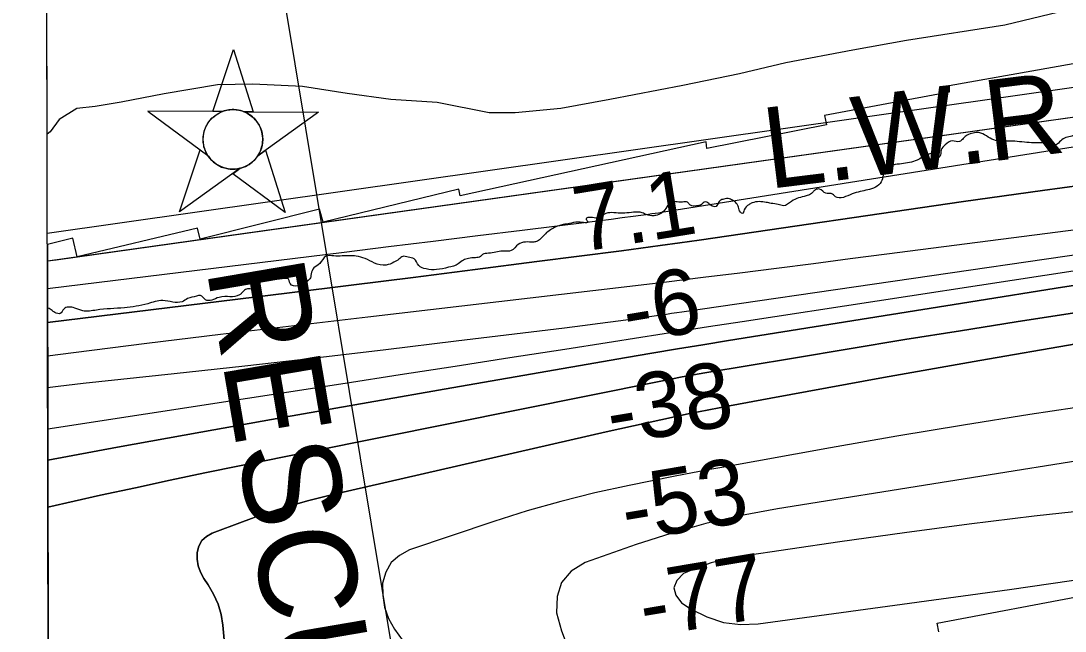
# Model space of a CAD drawing. Extents: x 3355677 to 3393573, y 612928 to 638357.
# Drawn here: x 3359768 to 3360838, y 623686 to 624311 of the extents above; entities that cross this region are included whole.
import ezdxf

# ---------------------------------------------------------------- set-up
doc = ezdxf.new("R2010")
doc.units = 0
for name, color, linetype in [('V-CHAN-NAID', 7, 'Continuous'), ('V-GRID-FRAM', 7, 'Continuous'), ('V-RIVR-EDGE', 7, 'Continuous'), ('V-RIVR-RANG', 7, 'Continuous'), ('V-RRAP-RVMT', 7, 'Continuous'), ('V-SITE-VEGE', 7, 'Continuous'), ('V-TOPO-DPTH', 7, 'Continuous'), ('V-TOPO-MAJR', 7, 'Continuous'), ('V-TOPO-MINR', 7, 'Continuous'), ('V-TOPO-WATR', 7, 'Continuous'), ('V-TOPO-WATR-IDEN', 7, 'Continuous')]:
    doc.layers.add(name, color=color, linetype=linetype)

msp = doc.modelspace()

# ---------------------------------------------------------------- linework, layer by layer
at = {"layer": 'V-CHAN-NAID'}
for points in [[(3359974.3, 624218), (3359964.7, 624218.1), (3359985.8, 624281.6), (3360006, 624217.8), (3359996.5, 624217.8), (3359994.9, 624218.4), (3359992.8, 624219), (3359990.7, 624219.5), (3359988.7, 624219.8), (3359987.5, 624219.9), (3359986, 624220), (3359984.3, 624220), (3359982.9, 624219.9), (3359981, 624219.7), (3359979.6, 624219.5), (3359977.9, 624219.1), (3359976.3, 624218.7), (3359975.3, 624218.4)], [(3359974.3, 624218), (3359897.8, 624218.5), (3359959.4, 624173.1), (3359958.2, 624175.1), (3359957.4, 624176.7), (3359956.6, 624178.6), (3359955.9, 624180.7), (3359955.5, 624182), (3359955.2, 624183.7), (3359954.9, 624185.1), (3359954.7, 624186.7), (3359954.6, 624188.4), (3359954.6, 624190), (3359954.7, 624192.1), (3359954.9, 624193.7), (3359955.3, 624195.9), (3359955.8, 624197.8), (3359956.4, 624199.7), (3359957, 624201.4), (3359957.8, 624203), (3359958.6, 624204.5), (3359959.6, 624206.3), (3359960.7, 624207.7), (3359961.7, 624209), (3359962.7, 624210.1), (3359964, 624211.5), (3359965, 624212.4), (3359966.8, 624213.8), (3359968, 624214.7), (3359969.7, 624215.8), (3359971.4, 624216.7), (3359972.8, 624217.4)], [(3359996.5, 624217.8), (3360072.9, 624217.3), (3360010.7, 624172.8), (3360011.7, 624174.3), (3360012.6, 624176.1), (3360013.3, 624177.7), (3360014.1, 624179.7), (3360014.6, 624181.4), (3360015, 624183.1), (3360015.4, 624185.1), (3360015.6, 624186.7), (3360015.7, 624188.9), (3360015.7, 624190.9), (3360015.5, 624193.2), (3360015.2, 624194.9), (3360014.7, 624197.1), (3360014.1, 624199.3), (3360013.3, 624201.3), (3360012.7, 624202.7), (3360011.7, 624204.6), (3360010.6, 624206.3), (3360009.4, 624208), (3360008.1, 624209.6), (3360006.9, 624211), (3360005.2, 624212.5), (3360003.5, 624213.9), (3360001.8, 624215.1), (3359999.9, 624216.2), (3359998.5, 624217)], [(3359992.7, 624159.9), (3359930.5, 624115.4), (3359951.6, 624178.8), (3359959.4, 624173.1), (3359960, 624172.2), (3359961.4, 624170.3), (3359962.6, 624168.9), (3359964, 624167.4), (3359965.4, 624166.2), (3359966.9, 624165), (3359968.3, 624164), (3359970, 624163), (3359971.7, 624162.1), (3359973.5, 624161.2), (3359974.9, 624160.7), (3359976.6, 624160.2), (3359978.8, 624159.6), (3359980.3, 624159.3), (3359982.3, 624159.1), (3359983.9, 624159), (3359985.7, 624158.9), (3359987.4, 624159), (3359989.1, 624159.2), (3359991, 624159.5)], [(3360010.7, 624172.8), (3360018.5, 624178.4), (3360038.8, 624114.6), (3359984.9, 624154.3), (3359992.7, 624159.9), (3359994.4, 624160.3), (3359996, 624160.9), (3359998.1, 624161.8), (3359999.9, 624162.7), (3360001.7, 624163.8), (3360003.5, 624165), (3360005, 624166.3), (3360006.3, 624167.4), (3360007.7, 624168.9), (3360008.9, 624170.3), (3360010, 624171.7)]]:
    msp.add_lwpolyline(points, close=True, dxfattribs=at)
msp.add_circle((3359985.2, 624189.5), 30.5, dxfattribs=at)
at = {"layer": 'V-GRID-FRAM'}
msp.add_lwpolyline([(3359767.9, 636495.9), (3391341.6, 636578.5), (3391397.2, 618394.8), (3359807.6, 618312.1), (3359767.9, 636495.9)], dxfattribs=at)
at = {"layer": 'V-RIVR-EDGE'}
msp.add_spline([(3361514.4, 624269.9), (3361505.3, 624274.5), (3361502.1, 624278.4), (3361496.5, 624283.3), (3361490.9, 624284.4), (3361483.1, 624283), (3361475.7, 624283.7), (3361471.5, 624284.4), (3361468, 624284.5), (3361456.3, 624283.8), (3361443.6, 624283.1), (3361441.5, 624281.3), (3361438.7, 624277.8), (3361435.5, 624275), (3361428.1, 624276.1), (3361404.5, 624279), (3361392.2, 624279), (3361369.3, 624278), (3361357.7, 624279.1), (3361353.4, 624279.1), (3361345, 624274.9), (3361330.5, 624271.8), (3361314.6, 624269.7), (3361302.7, 624270.4), (3361294.9, 624270.4), (3361282.6, 624268), (3361272, 624261), (3361254.3, 624251.9), (3361240.2, 624247.3), (3361214.2, 624245.3), (3361183.9, 624246.7), (3361168, 624247.5), (3361159.9, 624246.8), (3361142.6, 624243), (3361131, 624241.6), (3361126.7, 624237.7), (3361121.1, 624232.5), (3361115.1, 624231.1), (3361104.2, 624229.7), (3361086.5, 624225.5), (3361085.5, 624223.4), (3361069.3, 624226.2), (3361054.5, 624227), (3361050.3, 624230.2), (3361044.6, 624230.2), (3361039.7, 624229.1), (3361032.6, 624228.1), (3361024.9, 624228.8), (3361017.5, 624226), (3361008.3, 624225.3), (3361000.2, 624225.4), (3360993.9, 624223.3), (3360987.2, 624221.2), (3360979.8, 624221.2), (3360974.8, 624221.2), (3360970.9, 624217.7), (3360961.4, 624211.7), (3360953.7, 624206.4), (3360933.2, 624197.7), (3360914.2, 624192.1), (3360899.3, 624191.4), (3360889.8, 624191.8), (3360884.9, 624193.9), (3360880, 624196.8), (3360874, 624195.7), (3360867.6, 624194), (3360863.4, 624190.1), (3360862, 624184.5), (3360860.2, 624183.4), (3360856.3, 624186.6), (3360853.2, 624194.4), (3360849.3, 624194.4), (3360843.3, 624192.3), (3360837.3, 624190.9), (3360827.1, 624183.5), (3360817.9, 624185.6), (3360808.4, 624186), (3360798.6, 624186.4), (3360778.8, 624187.8), (3360764.7, 624188.9), (3360749.6, 624196.4), (3360743.6, 624196), (3360737.6, 624193.9), (3360733.4, 624190.4), (3360729.8, 624187.3), (3360722.4, 624188), (3360715, 624183.8), (3360710.8, 624178.9), (3360709.4, 624171.8), (3360707.6, 624170.8), (3360706.2, 624171.8), (3360704.4, 624175.3), (3360701.6, 624175.3), (3360697, 624174), (3360686.1, 624168.3), (3360670.2, 624164.5), (3360654.7, 624159.6), (3360651.5, 624152.9), (3360649.4, 624145.9), (3360643.4, 624140.6), (3360635.6, 624137.8), (3360619.8, 624133.6), (3360602.5, 624130.8), (3360598.3, 624134), (3360592.6, 624134.4), (3360586.3, 624138.6), (3360582.1, 624137.9), (3360580, 624136.2), (3360577.1, 624133.4), (3360572.5, 624131.6), (3360557.4, 624126), (3360549.3, 624121.5), (3360544, 624122.9), (3360536.6, 624124), (3360531.7, 624125), (3360517.2, 624124.4), (3360513.7, 624122.6), (3360509.1, 624117.3), (3360507.3, 624113.5), (3360505.2, 624114.9), (3360503.1, 624120.2), (3360501.7, 624123.3), (3360498.2, 624126.5), (3360494, 624128.6), (3360488, 624128.3), (3360484.4, 624126.9), (3360481.6, 624122.7), (3360480.2, 624120.9), (3360474.9, 624122), (3360470.7, 624125.2), (3360467.9, 624125.2), (3360464.3, 624122), (3360462.6, 624121.7), (3360453.4, 624122.4), (3360451, 624125.2), (3360445.7, 624125.2), (3360433.3, 624124.9), (3360428.7, 624118.6), (3360418.5, 624111.6), (3360414.3, 624111.2), (3360406.9, 624113.4), (3360402.3, 624114.8), (3360384.3, 624113.8), (3360367.1, 624113.5), (3360356.8, 624108.9), (3360349.8, 624109.6), (3360347, 624108.2), (3360348.7, 624105.4), (3360339.2, 624104.7), (3360330, 624103.3), (3360323.7, 624102.3), (3360314.5, 624099.1), (3360304.3, 624091.8), (3360297.2, 624085.4), (3360293.4, 624084.4), (3360284.9, 624084.4), (3360277.5, 624082), (3360270.4, 624075.6), (3360261.6, 624075), (3360247.2, 624072.9), (3360240.8, 624071.5), (3360239, 624069.7), (3360233.8, 624068.3), (3360226.4, 624067.6), (3360221.4, 624065.9), (3360216.1, 624062), (3360205.9, 624058.5), (3360193.9, 624056.1), (3360183, 624056.8), (3360175.6, 624060.4), (3360170.7, 624067.1), (3360164.7, 624068.8), (3360159.1, 624069.6), (3360155.2, 624066.8), (3360150.2, 624063.6), (3360142.1, 624060.8), (3360130.1, 624062.9), (3360120.6, 624067.5), (3360111.5, 624070), (3360097, 624070.1), (3360088.6, 624070.1), (3360080.5, 624069.8), (3360074.1, 624062.4), (3360068.1, 624057.8), (3360065.3, 624051.8), (3360064.9, 624048.7), (3360062.4, 624045.1), (3360043.8, 624042), (3360041, 624047), (3360038.5, 624047), (3360027.6, 624046.6), (3360017, 624046.7), (3360013.1, 624043.1), (3360010.6, 624037.2), (3360007.5, 624036.1), (3359997.9, 624035.8), (3359994.1, 624031.9), (3359991.9, 624030.2), (3359971.1, 624027.7), (3359957, 624025.3), (3359951.8, 624029.6), (3359947.9, 624028.9), (3359938.7, 624026.4), (3359933.1, 624023.3), (3359913.3, 624024.4), (3359897.8, 624021.2), (3359873.9, 624017.1), (3359845.3, 624014.7), (3359831.2, 624014), (3359823.1, 624016.8), (3359811.8, 624015.8), (3359808.3, 624011.2), (3359802.7, 624012.3), (3359800.9, 624013.4), (3359796.7, 624016.2), (3359795.1, 624016.8)], degree=3, dxfattribs=at)
at = {"layer": 'V-RIVR-RANG'}
msp.add_line((3359979.7, 624681.3), (3360196.7, 623374.1), dxfattribs=at)
at = {"layer": 'V-RRAP-RVMT'}
for p, q in [((3360846.1, 624267), (3360719.1, 624244.2)), ((3360719.1, 624244.2), (3360719.2, 624237.9)), ((3360719.2, 624237.9), (3360591.4, 624214)), ((3360591.4, 624214), (3360593.3, 624204.5)), ((3360593.3, 624204.5), (3360470.6, 624180)), ((3360470.2, 624187), (3360218, 624131.8)), ((3360470.6, 624180), (3360470.2, 624187)), ((3360216.5, 624138.6), (3360077.6, 624104.6)), ((3360218, 624131.8), (3360216.5, 624138.6)), ((3360074, 624118.2), (3359951.7, 624087.2)), ((3360077.6, 624104.6), (3360074, 624118.2)), ((3359948.7, 624098.5), (3359825.4, 624069.2)), ((3359951.7, 624087.2), (3359948.7, 624098.5)), ((3359821, 624088.4), (3359795, 624082)), ((3359825.4, 624069.2), (3359821, 624088.4)), ((3359795, 624082), (3359796.2, 623514.4)), ((3360706.7, 623694.1), (3360940.1, 623738.3)), ((3360708.5, 623685.3), (3360706.7, 623694.1))]:
    msp.add_line(p, q, dxfattribs=at)
at = {"layer": 'V-SITE-VEGE'}
for p, q in [((3359794.7, 624194.9), (3359794.4, 624337.1)), ((3360831.3, 624319.8), (3360776.1, 624306.4)), ((3360776.1, 624306.4), (3360675.4, 624290.7)), ((3360675.4, 624290.7), (3360620.2, 624280.7)), ((3360620.2, 624280.7), (3360551.7, 624268)), ((3360551.7, 624268), (3360504.2, 624256.6)), ((3360504.2, 624256.6), (3360446.2, 624244.6)), ((3359969.2, 624245.3), (3359914.6, 624236.1)), ((3360005.5, 624246.1), (3359969.2, 624245.3)), ((3360056.6, 624243.5), (3360005.5, 624246.1)), ((3360102.1, 624236.6), (3360056.6, 624243.5)), ((3360446.2, 624244.6), (3360371.4, 624230.4)), ((3359914.6, 624236.1), (3359870.6, 624227.6)), ((3360146.9, 624230.5), (3360102.1, 624236.6)), ((3359825.2, 624221.2), (3359807, 624209.9)), ((3359844, 624223.3), (3359825.2, 624221.2)), ((3359870.6, 624227.6), (3359844, 624223.3)), ((3360194.4, 624227.1), (3360146.9, 624230.5)), ((3360247.6, 624216.8), (3360194.4, 624227.1)), ((3360321, 624221.2), (3360274.2, 624216.8)), ((3360371.4, 624230.4), (3360321, 624221.2)), ((3360274.2, 624216.8), (3360247.6, 624216.8)), ((3359807, 624209.9), (3359798, 624197.3)), ((3359798, 624197.3), (3359794.7, 624194.9))]:
    msp.add_line(p, q, dxfattribs=at)
at = {"layer": 'V-TOPO-DPTH'}
for points in [[(3360996.5, 624233), (3359804.2, 624065.9), (3359795, 624064.7), (3359795.1, 624002)], [(3359795.1, 624002), (3360043.1, 624032.4), (3360106.4, 624040.2), (3360169.8, 624048.1), (3360233.2, 624056.2), (3360296.5, 624064.3), (3360383.3, 624075.5), (3360403.2, 624078.1), (3360423.1, 624080.8), (3360443, 624083.6), (3360462.9, 624086.4), (3360733.8, 624125.8), (3360814.6, 624137.2), (3360895.4, 624148.1)], [(3359795.1, 624002), (3360043.1, 624032.4), (3360106.4, 624040.2), (3360169.8, 624048.1), (3360233.2, 624056.2), (3360296.5, 624064.3), (3360383.3, 624075.5), (3360403.2, 624078.1), (3360423.1, 624080.8), (3360443, 624083.6), (3360462.9, 624086.4), (3360733.8, 624125.8), (3360814.6, 624137.2), (3360895.4, 624148.1)], [(3359795.3, 623935.2), (3359795.5, 623861.1), (3359866.8, 623874.2), (3359952.3, 623889.7), (3360038, 623905.1), (3360123.6, 623920.2), (3360209.3, 623935.2), (3360388.4, 623966.1), (3360414.5, 623970.6), (3360440.6, 623975), (3360466.7, 623979.2), (3360492.8, 623983.5), (3360747.6, 624024.2), (3360828.8, 624037.1), (3360910, 624049.9), (3360991.2, 624062.6), (3361072.4, 624075.2), (3361173.9, 624090.9), (3361204.4, 624095.4), (3361234.9, 624099.8), (3361265.5, 624103.9), (3361951, 624138.5)], [(3361951, 624138.5), (3361265.5, 624103.9), (3361234.9, 624099.8), (3361204.4, 624095.4), (3361173.9, 624090.9), (3361072.4, 624075.2), (3360991.2, 624062.6), (3360910, 624049.9), (3360828.8, 624037.1), (3360747.6, 624024.2), (3360492.8, 623983.5), (3360466.7, 623979.2), (3360440.6, 623975), (3360414.5, 623970.6), (3360388.4, 623966.1), (3360209.3, 623935.2), (3360123.6, 623920.2), (3360038, 623905.1), (3359952.3, 623889.7), (3359866.8, 623874.2), (3359795.5, 623861.1)], [(3361093.7, 624106.8), (3360445.2, 624012.6), (3360439.9, 624011.9), (3360434.6, 624011.1), (3360429.4, 624010.3), (3360424.1, 624009.6), (3360398.1, 624005.9), (3360379.9, 624003.3), (3360361.6, 624000.8), (3360343.3, 623998.5), (3360325, 623996.2), (3360213.9, 623982.7), (3360141.8, 623974), (3360069.5, 623965.6), (3359997.3, 623957.4), (3359925, 623949.5), (3359831.8, 623939.4), (3359806.2, 623936.5), (3359795.3, 623935.2), (3359795.1, 624002)], [(3361093.7, 624106.8), (3360445.2, 624012.6), (3360439.9, 624011.9), (3360434.6, 624011.1), (3360429.4, 624010.3), (3360424.1, 624009.6), (3360398.1, 624005.9), (3360379.9, 624003.3), (3360361.6, 624000.8), (3360343.3, 623998.5), (3360325, 623996.2), (3360213.9, 623982.7), (3360141.8, 623974), (3360069.5, 623965.6), (3359997.3, 623957.4), (3359925, 623949.5), (3359831.8, 623939.4), (3359806.2, 623936.5), (3359795.3, 623935.2)], [(3359795.5, 623861.1), (3359795.6, 623812.8), (3359849.6, 623825), (3359885.2, 623832.8), (3359920.7, 623840.5), (3359956.3, 623848), (3359992, 623855.3), (3360422, 623941.7), (3360433.7, 623944), (3360445.4, 623946.2), (3360457.1, 623948.3), (3360468.8, 623950.4), (3360559.4, 623965.6), (3360616.5, 623975.1), (3360673.6, 623984.5), (3360730.7, 623993.5), (3360787.8, 624002.5), (3361207.2, 624067.1), (3361223.6, 624069.5), (3361240, 624071.9), (3361256.4, 624074), (3361948, 624112.6)], [(3359798, 622708.4), (3359795.6, 623812.8), (3359849.6, 623825), (3359885.2, 623832.8), (3359920.7, 623840.5), (3359956.3, 623848), (3359992, 623855.3), (3360422, 623941.7), (3360433.7, 623944), (3360445.4, 623946.2), (3360457.1, 623948.3), (3360468.8, 623950.4), (3360559.4, 623965.6), (3360616.5, 623975.1), (3360673.6, 623984.5), (3360730.7, 623993.5), (3360787.8, 624002.5), (3361207.2, 624067.1), (3361223.6, 624069.5), (3361240, 624071.9), (3361256.4, 624074), (3361948, 624112.6)], [(3360849.2, 623980.2), (3360750.5, 623963.2), (3360651.8, 623945.6), (3360536.2, 623924.6), (3360493.9, 623916.6), (3360451.7, 623908.3), (3360409.6, 623899.3), (3360367.5, 623890), (3360086.1, 623825.5), (3360062.9, 623819.7), (3360040, 623813.2), (3360017.3, 623805.9), (3359994.8, 623798), (3359963.8, 623786.3), (3359958, 623782.9), (3359953.3, 623778.7), (3359950.3, 623773.1), (3359948.5, 623766.6), (3359948.5, 623759.6), (3359949.4, 623752.7), (3359951.8, 623746.3), (3359955.2, 623740), (3359959.8, 623733.4), (3359965.4, 623723.7), (3359970, 623713.7), (3359973, 623703), (3359974.9, 623692), (3360032.3, 623068.8)], [(3360032.3, 623068.8), (3359974.9, 623692), (3359973, 623703), (3359970, 623713.7), (3359965.4, 623723.7), (3359959.8, 623733.4), (3359955.2, 623740), (3359951.8, 623746.3), (3359949.4, 623752.7), (3359948.5, 623759.6), (3359948.5, 623766.6), (3359950.3, 623773.1), (3359953.3, 623778.7), (3359958, 623782.9), (3359963.8, 623786.3), (3359994.8, 623798), (3360017.3, 623805.9), (3360040, 623813.2), (3360062.9, 623819.7), (3360086.1, 623825.5), (3360367.5, 623890), (3360409.6, 623899.3), (3360451.7, 623908.3), (3360493.9, 623916.6), (3360536.2, 623924.6), (3360651.8, 623945.6), (3360750.5, 623963.2), (3360849.2, 623980.2)]]:
    msp.add_lwpolyline(points, dxfattribs=at)
at = {"layer": 'V-TOPO-MAJR'}
msp.add_lwpolyline([(3360870.2, 623917.9), (3360801.8, 623907.7), (3360733.6, 623897), (3360665.5, 623885.6), (3360597.4, 623873.7), (3360486.2, 623853.6), (3360473.8, 623851.3), (3360461.4, 623849), (3360449, 623846.6), (3360436.7, 623844.2), (3360391, 623835.1), (3360356, 623827.4), (3360321.2, 623818.8), (3360286.7, 623809), (3360252.5, 623798.2), (3360166.1, 623769.2), (3360155.7, 623763.5), (3360147.3, 623756.2), (3360141.9, 623746.4), (3360138.5, 623735.1), (3360138.6, 623722.5), (3360140.3, 623710.4), (3360144.7, 623699), (3360150.8, 623688), (3360159.6, 623675.7)], dxfattribs=at)
at = {"layer": 'V-TOPO-MINR'}
for points in [[(3361000.5, 624264.6), (3359794.9, 624093.1)], [(3360996.5, 624233), (3359795, 624064.7)], [(3360867.5, 624184.8), (3360424.4, 624114.6), (3360421.1, 624114.1), (3360417.7, 624113.6), (3360414.4, 624113.1), (3360411, 624112.6), (3360395.3, 624110.5), (3360384.1, 624109), (3360372.8, 624107.5), (3360361.6, 624106.1), (3360350.4, 624104.7), (3360281.6, 624096.2), (3360236, 624090.6), (3360190.3, 624085), (3360144.7, 624079.4), (3360099.1, 624073.8), (3359795.1, 624036.4)], [(3361911.4, 624147), (3361270, 624118.5), (3361232.5, 624113.5), (3361195, 624108.1), (3361157.6, 624102.5), (3361128.9, 624098), (3361077.2, 624090), (3361025.4, 624082.1), (3360973.7, 624074.1), (3360921.9, 624066.2), (3360507.1, 624002.7), (3360472.4, 623997.4), (3360437.8, 623992), (3360403.2, 623986.6), (3360368.5, 623981.2), (3360325.3, 623974.5), (3360269, 623965.7), (3360212.8, 623957), (3360156.5, 623948.3), (3360100.3, 623939.6), (3359795.4, 623892.6)], [(3361202, 624142.4), (3360655.2, 624071.9), (3360617.5, 624067.1), (3360579.9, 624062.2), (3360542.3, 624057.4), (3360504.6, 624052.6), (3360467, 624047.9), (3360429.3, 624043.3), (3360391.7, 624038.8), (3360354, 624034.3), (3360123.3, 624007.6), (3360047.9, 623998.7), (3359972.5, 623989.7), (3359897.1, 623980.4), (3359821.7, 623970.9), (3359795.2, 623967.6)], [(3361951, 624138.5), (3361265.5, 624103.9), (3361234.9, 624099.8), (3361204.4, 624095.4), (3361173.9, 624090.9), (3361072.4, 624075.2), (3360991.2, 624062.6), (3360910, 624049.9), (3360828.8, 624037.1), (3360747.6, 624024.2), (3360492.8, 623983.5), (3360466.7, 623979.2), (3360440.6, 623975), (3360414.5, 623970.6), (3360388.4, 623966.1), (3360209.3, 623935.2), (3360123.6, 623920.2), (3360038, 623905.1), (3359952.3, 623889.7), (3359866.8, 623874.2), (3359795.5, 623861.1)], [(3361093.7, 624106.8), (3360445.2, 624012.6), (3360439.9, 624011.9), (3360434.6, 624011.1), (3360429.4, 624010.3), (3360424.1, 624009.6), (3360398.1, 624005.9), (3360379.9, 624003.3), (3360361.6, 624000.8), (3360343.3, 623998.5), (3360325, 623996.2), (3360213.9, 623982.7), (3360141.8, 623974), (3360069.5, 623965.6), (3359997.3, 623957.4), (3359925, 623949.5), (3359831.8, 623939.4), (3359806.2, 623936.5), (3359795.3, 623935.2)], [(3361948, 624112.6), (3361256.4, 624074), (3361240, 624071.9), (3361223.6, 624069.5), (3361207.2, 624067.1), (3360787.8, 624002.5), (3360730.7, 623993.5), (3360673.6, 623984.5), (3360616.5, 623975.1), (3360559.4, 623965.6), (3360468.8, 623950.4), (3360457.1, 623948.3), (3360445.4, 623946.2), (3360433.7, 623944), (3360422, 623941.7), (3359992, 623855.3), (3359956.3, 623848), (3359920.7, 623840.5), (3359885.2, 623832.8), (3359849.6, 623825), (3359795.6, 623812.8)], [(3360032.3, 623068.8), (3359974.9, 623692), (3359973, 623703), (3359970, 623713.7), (3359965.4, 623723.7), (3359959.8, 623733.4), (3359955.2, 623740), (3359951.8, 623746.3), (3359949.4, 623752.7), (3359948.5, 623759.6), (3359948.5, 623766.6), (3359950.3, 623773.1), (3359953.3, 623778.7), (3359958, 623782.9), (3359963.8, 623786.3), (3359994.8, 623798), (3360017.3, 623805.9), (3360040, 623813.2), (3360062.9, 623819.7), (3360086.1, 623825.5), (3360367.5, 623890), (3360409.6, 623899.3), (3360451.7, 623908.3), (3360493.9, 623916.6), (3360536.2, 623924.6), (3360651.8, 623945.6), (3360750.5, 623963.2), (3360849.2, 623980.2)], [(3361068.9, 623895.2), (3360543, 623811.2), (3360506.2, 623804.3), (3360469.8, 623796.1), (3360433.8, 623786), (3360398.2, 623774.6), (3360346, 623756.2), (3360331.9, 623747.2), (3360321.7, 623735.9), (3360317.3, 623721.4), (3360316.7, 623704.8), (3360321.9, 623686.1), (3360328.6, 623668.2)], [(3360872.4, 623811), (3360806, 623803.5), (3360739.6, 623795.5), (3360673.3, 623786.7), (3360607, 623777.4), (3360505.3, 623762.5), (3360490.2, 623759.6), (3360475.3, 623755.8)], [(3360475.3, 623755.8), (3360460.9, 623750.7), (3360446.7, 623744.8), (3360440.1, 623737.7), (3360436.9, 623730.4), (3360439.1, 623722.8), (3360444.8, 623714.9), (3360454.7, 623708.6), (3360470.9, 623700.5), (3360487.7, 623694.9), (3360505.3, 623692.9), (3360523.4, 623693.4), (3360781, 623728.5), (3360865.6, 623740.9)]]:
    msp.add_lwpolyline(points, dxfattribs=at)
at = {"layer": 'V-TOPO-WATR'}
msp.add_lwpolyline([(3360895.4, 624148.1), (3360814.6, 624137.2), (3360733.8, 624125.8), (3360462.9, 624086.4), (3360443, 624083.6), (3360423.1, 624080.8), (3360403.2, 624078.1), (3360383.3, 624075.5), (3360296.5, 624064.3), (3360233.2, 624056.2), (3360169.8, 624048.1), (3360106.4, 624040.2), (3360043.1, 624032.4), (3359795.1, 624002)], dxfattribs=at)

# ---------------------------------------------------------------- texts
at = {"layer": 'V-CHAN-NAID'}
msp.add_text('RESCUE "190" (188.6)', height=100, rotation=279.6705, dxfattribs=at).set_placement((3359957.9, 624057.1))
at = {"layer": 'V-RIVR-RANG'}
for s, rotation, p in [('7.1', 9.2383, (3360340, 624073.8)), ('-6', 9.5213, (3360389.8, 623980.4)), ('-38', 9.5213, (3360373.3, 623876.2)), ('-53', 9.5213, (3360388.6, 623777.4)), ('-77', 9.5213, (3360407, 623679.1))]:
    msp.add_text(s, height=67, rotation=rotation, dxfattribs=at).set_placement(p)
at = {"layer": 'V-TOPO-WATR-IDEN'}
msp.add_text('L.W.R.P.', height=83, rotation=7.0318, dxfattribs=at).set_placement((3360534.2, 624138.7))

doc.saveas('drawing.dxf')
